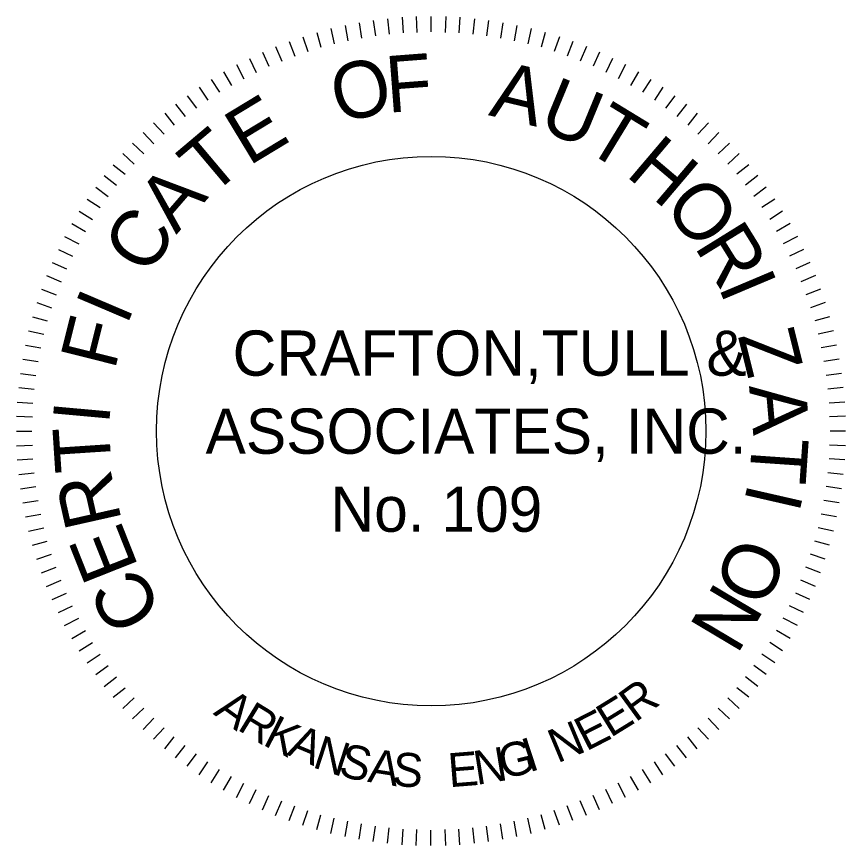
# Model space of a CAD drawing. Extents: x 6028666 to 6031787, y 5366484 to 5368484.
# Drawn here: x 6031045.9 to 6031317.1, y 5366759.6 to 5367030.8 of the extents above; entities that cross this region are included whole.
import ezdxf

# ---------------------------------------------------------------- set-up
doc = ezdxf.new("R2010")
doc.units = 0
doc.layers.add('R_Border Prem', color=7, linetype='Continuous')

msp = doc.modelspace()

# ---------------------------------------------------------------- linework, layer by layer
at = {"layer": 'R_Border Prem'}
for p, q in [((6031162.65, 5367029.51), (6031163.39, 5367024.52)), ((6031167.28, 5367030.07), (6031167.83, 5367025.07)), ((6031172.09, 5367030.62), (6031172.46, 5367025.44)), ((6031176.71, 5367030.81), (6031176.9, 5367025.63)), ((6031181.52, 5367030.81), (6031181.52, 5367025.81)), ((6031186.33, 5367030.81), (6031186.15, 5367025.63)), ((6031190.96, 5367030.62), (6031190.59, 5367025.44)), ((6031195.77, 5367030.07), (6031195.21, 5367025.07)), ((6031200.39, 5367029.51), (6031199.65, 5367024.52)), ((6031148.78, 5367026.92), (6031149.89, 5367021.93)), ((6031153.4, 5367027.85), (6031154.33, 5367022.85)), ((6031158.03, 5367028.77), (6031158.77, 5367023.78)), ((6031205.02, 5367028.77), (6031204.28, 5367023.78)), ((6031209.64, 5367027.85), (6031208.72, 5367022.85)), ((6031214.27, 5367026.92), (6031213.16, 5367021.93)), ((6031139.53, 5367024.15), (6031141.19, 5367019.34)), ((6031144.15, 5367025.63), (6031145.45, 5367020.82)), ((6031218.89, 5367025.63), (6031217.6, 5367020.82)), ((6031223.52, 5367024.15), (6031221.85, 5367019.34)), ((6031130.65, 5367021), (6031132.68, 5367016.19)), ((6031135.09, 5367022.67), (6031136.94, 5367017.86)), ((6031227.96, 5367022.67), (6031226.11, 5367017.86)), ((6031232.4, 5367021), (6031230.36, 5367016.19)), ((6031126.39, 5367019.15), (6031128.43, 5367014.53)), ((6031236.65, 5367019.15), (6031234.62, 5367014.53)), ((6031122.14, 5367017.12), (6031124.36, 5367012.49)), ((6031240.91, 5367017.12), (6031238.69, 5367012.49)), ((6031113.63, 5367012.68), (6031116.22, 5367008.24)), ((6031117.88, 5367015.08), (6031120.29, 5367010.46)), ((6031245.16, 5367015.08), (6031242.76, 5367010.46)), ((6031249.42, 5367012.68), (6031246.83, 5367008.24)), ((6031109.56, 5367010.27), (6031112.33, 5367006.02)), ((6031253.49, 5367010.27), (6031250.71, 5367006.02)), ((6031105.67, 5367007.68), (6031108.45, 5367003.43)), ((6031257.37, 5367007.68), (6031254.6, 5367003.43)), ((6031101.79, 5367004.91), (6031104.75, 5367000.84)), ((6031261.26, 5367004.91), (6031258.3, 5367000.84)), ((6031097.9, 5367002.13), (6031101.05, 5366998.06)), ((6031265.14, 5367002.13), (6031262, 5366998.06)), ((6031094.39, 5366999.17), (6031097.53, 5366995.29)), ((6031268.66, 5366999.17), (6031265.51, 5366995.29)), ((6031090.69, 5366996.03), (6031094.2, 5366992.33)), ((6031272.36, 5366996.03), (6031268.84, 5366992.33)), ((6031087.36, 5366992.88), (6031090.87, 5366989.18)), ((6031275.69, 5366992.88), (6031272.17, 5366989.18)), ((6031083.84, 5366989.37), (6031087.54, 5366985.85)), ((6031279.2, 5366989.37), (6031275.5, 5366985.85)), ((6031080.7, 5366986.04), (6031084.4, 5366982.52)), ((6031282.35, 5366986.04), (6031278.65, 5366982.52)), ((6031077.55, 5366982.34), (6031081.44, 5366979.19)), ((6031285.49, 5366982.34), (6031281.61, 5366979.19)), ((6031074.59, 5366978.82), (6031078.66, 5366975.68)), ((6031288.45, 5366978.82), (6031284.38, 5366975.68)), ((6031071.82, 5366974.94), (6031075.89, 5366971.98)), ((6031291.23, 5366974.94), (6031287.16, 5366971.98)), ((6031069.04, 5366971.05), (6031073.3, 5366968.28)), ((6031294, 5366971.05), (6031289.75, 5366968.28)), ((6031066.45, 5366967.17), (6031070.71, 5366964.39)), ((6031296.59, 5366967.17), (6031292.34, 5366964.39)), ((6031064.05, 5366963.1), (6031068.49, 5366960.51)), ((6031299, 5366963.1), (6031294.56, 5366960.51)), ((6031061.64, 5366958.84), (6031066.27, 5366956.44)), ((6031301.4, 5366958.84), (6031296.78, 5366956.44)), ((6031059.61, 5366954.59), (6031064.23, 5366952.37)), ((6031303.44, 5366954.59), (6031298.81, 5366952.37)), ((6031057.57, 5366950.33), (6031062.2, 5366948.3)), ((6031305.47, 5366950.33), (6031300.85, 5366948.3)), ((6031055.72, 5366946.08), (6031060.53, 5366944.04)), ((6031307.32, 5366946.08), (6031302.51, 5366944.04)), ((6031054.06, 5366941.64), (6031058.87, 5366939.79)), ((6031308.99, 5366941.64), (6031304.18, 5366939.79)), ((6031052.58, 5366937.2), (6031057.39, 5366935.53)), ((6031310.47, 5366937.2), (6031305.66, 5366935.53)), ((6031051.1, 5366932.57), (6031055.91, 5366931.28)), ((6031311.95, 5366932.57), (6031307.14, 5366931.28)), ((6031049.8, 5366927.95), (6031054.8, 5366926.84)), ((6031313.24, 5366927.95), (6031308.25, 5366926.84)), ((6031048.88, 5366923.32), (6031053.87, 5366922.4)), ((6031314.17, 5366923.32), (6031309.17, 5366922.4)), ((6031047.95, 5366918.7), (6031052.95, 5366917.96)), ((6031315.09, 5366918.7), (6031310.1, 5366917.96)), ((6031047.21, 5366914.07), (6031052.21, 5366913.33)), ((6031315.83, 5366914.07), (6031310.84, 5366913.33)), ((6031046.66, 5366909.45), (6031051.65, 5366908.89)), ((6031316.39, 5366909.45), (6031311.39, 5366908.89)), ((6031046.1, 5366904.64), (6031051.28, 5366904.27)), ((6031316.94, 5366904.64), (6031311.76, 5366904.27)), ((6031045.92, 5366900.01), (6031051.1, 5366899.83)), ((6031317.13, 5366900.01), (6031311.95, 5366899.83)), ((6031045.92, 5366895.2), (6031050.91, 5366895.2)), ((6031317.13, 5366895.2), (6031312.13, 5366895.2)), ((6031045.92, 5366890.39), (6031051.1, 5366890.58)), ((6031317.13, 5366890.39), (6031311.95, 5366890.58)), ((6031046.1, 5366885.77), (6031051.28, 5366886.14)), ((6031316.94, 5366885.77), (6031311.76, 5366886.14)), ((6031046.66, 5366880.96), (6031051.65, 5366881.51)), ((6031316.39, 5366880.96), (6031311.39, 5366881.51)), ((6031047.21, 5366876.33), (6031052.21, 5366877.07)), ((6031315.83, 5366876.33), (6031310.84, 5366877.07)), ((6031047.95, 5366871.71), (6031052.95, 5366872.45)), ((6031315.09, 5366871.71), (6031310.1, 5366872.45)), ((6031048.88, 5366867.08), (6031053.87, 5366868.01)), ((6031314.17, 5366867.08), (6031309.17, 5366868.01)), ((6031049.8, 5366862.46), (6031054.8, 5366863.57)), ((6031313.24, 5366862.46), (6031308.25, 5366863.57)), ((6031051.1, 5366857.83), (6031055.91, 5366859.13)), ((6031311.95, 5366857.83), (6031307.14, 5366859.13)), ((6031052.58, 5366853.21), (6031057.39, 5366854.87)), ((6031310.47, 5366853.21), (6031305.66, 5366854.87)), ((6031054.06, 5366848.77), (6031058.87, 5366850.62)), ((6031308.99, 5366848.77), (6031304.18, 5366850.62)), ((6031055.72, 5366844.33), (6031060.53, 5366846.36)), ((6031307.32, 5366844.33), (6031302.51, 5366846.36)), ((6031057.57, 5366840.07), (6031062.2, 5366842.11)), ((6031305.47, 5366840.07), (6031300.85, 5366842.11)), ((6031059.61, 5366835.82), (6031064.23, 5366838.04)), ((6031303.44, 5366835.82), (6031298.81, 5366838.04)), ((6031061.64, 5366831.56), (6031066.27, 5366833.97)), ((6031301.4, 5366831.56), (6031296.78, 5366833.97)), ((6031064.05, 5366827.31), (6031068.49, 5366829.9)), ((6031299, 5366827.31), (6031294.56, 5366829.9)), ((6031066.45, 5366823.24), (6031070.71, 5366826.01)), ((6031296.59, 5366823.24), (6031292.34, 5366826.01)), ((6031069.04, 5366819.35), (6031073.3, 5366822.13)), ((6031294, 5366819.35), (6031289.75, 5366822.13)), ((6031071.82, 5366815.47), (6031075.89, 5366818.43)), ((6031291.23, 5366815.47), (6031287.16, 5366818.43)), ((6031074.59, 5366811.58), (6031078.66, 5366814.73)), ((6031288.45, 5366811.58), (6031284.38, 5366814.73)), ((6031077.55, 5366808.07), (6031081.44, 5366811.21)), ((6031285.49, 5366808.07), (6031281.61, 5366811.21)), ((6031080.7, 5366804.37), (6031084.4, 5366807.88)), ((6031282.35, 5366804.37), (6031278.65, 5366807.88)), ((6031083.84, 5366801.04), (6031087.54, 5366804.55)), ((6031279.2, 5366801.04), (6031275.5, 5366804.55)), ((6031087.36, 5366797.52), (6031090.87, 5366801.22)), ((6031275.69, 5366797.52), (6031272.17, 5366801.22)), ((6031090.69, 5366794.38), (6031094.2, 5366798.08)), ((6031272.36, 5366794.38), (6031268.84, 5366798.08)), ((6031094.39, 5366791.23), (6031097.53, 5366795.12)), ((6031268.66, 5366791.23), (6031265.51, 5366795.12)), ((6031097.9, 5366788.27), (6031101.05, 5366792.34)), ((6031265.14, 5366788.27), (6031262, 5366792.34)), ((6031101.79, 5366785.5), (6031104.75, 5366789.57)), ((6031261.26, 5366785.5), (6031258.3, 5366789.57)), ((6031105.67, 5366782.72), (6031108.45, 5366786.98)), ((6031257.37, 5366782.72), (6031254.6, 5366786.98)), ((6031109.56, 5366780.13), (6031112.33, 5366784.39)), ((6031113.63, 5366777.73), (6031116.22, 5366782.17)), ((6031249.42, 5366777.73), (6031246.83, 5366782.17)), ((6031253.49, 5366780.13), (6031250.71, 5366784.39)), ((6031117.88, 5366775.32), (6031120.29, 5366779.95)), ((6031245.16, 5366775.32), (6031242.76, 5366779.95)), ((6031122.14, 5366773.29), (6031124.36, 5366777.91)), ((6031240.91, 5366773.29), (6031238.69, 5366777.91)), ((6031126.39, 5366771.25), (6031128.43, 5366775.88)), ((6031130.65, 5366769.4), (6031132.68, 5366774.21)), ((6031232.4, 5366769.4), (6031230.36, 5366774.21)), ((6031236.65, 5366771.25), (6031234.62, 5366775.88)), ((6031135.09, 5366767.74), (6031136.94, 5366772.55)), ((6031227.96, 5366767.74), (6031226.11, 5366772.55)), ((6031139.53, 5366766.26), (6031141.19, 5366771.07)), ((6031144.15, 5366764.78), (6031145.45, 5366769.59)), ((6031218.89, 5366764.78), (6031217.6, 5366769.59)), ((6031223.52, 5366766.26), (6031221.85, 5366771.07)), ((6031148.78, 5366763.48), (6031149.89, 5366768.48)), ((6031153.4, 5366762.56), (6031154.33, 5366767.55)), ((6031158.03, 5366761.63), (6031158.77, 5366766.63)), ((6031162.65, 5366760.89), (6031163.39, 5366765.89)), ((6031200.39, 5366760.89), (6031199.65, 5366765.89)), ((6031205.02, 5366761.63), (6031204.28, 5366766.63)), ((6031209.64, 5366762.56), (6031208.72, 5366767.55)), ((6031214.27, 5366763.48), (6031213.16, 5366768.48)), ((6031167.28, 5366760.34), (6031167.83, 5366765.33)), ((6031172.09, 5366759.78), (6031172.46, 5366764.96)), ((6031176.71, 5366759.6), (6031176.9, 5366764.78)), ((6031181.52, 5366759.6), (6031181.52, 5366764.59)), ((6031186.33, 5366759.6), (6031186.15, 5366764.78)), ((6031190.96, 5366759.78), (6031190.59, 5366764.96)), ((6031195.77, 5366760.34), (6031195.21, 5366765.33))]:
    msp.add_line(p, q, dxfattribs=at)
msp.add_circle((6031181.6, 5366895.16), 89.89, dxfattribs=at)

# ---------------------------------------------------------------- texts
for s, height, rotation, p in [('F', 18.5, 4.3732, (6031167.36, 5366999.31)), ('O', 18.5, 13.3113, (6031151.26, 5366995.8)), ('A', 18.5, 346.4969, (6031200.1, 5366998.57)), ('U', 18.5, 337.5588, (6031216.01, 5366994.32)), ('E', 18.5, 31.1876, (6031121.85, 5366981.74)), ('T', 18.5, 328.6206, (6031231, 5366987.66)), ('T', 18.5, 40.1257, (6031109.27, 5366971.56)), ('H', 18.5, 319.6825, (6031244.87, 5366978.96)), ('A', 18.5, 49.0639, (6031098.17, 5366959.35)), ('O', 18.5, 310.7444, (6031257.08, 5366968.23)), ('C', 18.5, 58.002, (6031089.1, 5366945.48)), ('R', 18.5, 301.8062, (6031267.44, 5366955.65)), ('I', 18.5, 292.8681, (6031275.4, 5366942.52)), ('I', 18.5, 66.9402, (6031081.89, 5366929.38)), ('F', 18.5, 75.8783, (6031078, 5366914.77)), ('Z', 18.5, 283.9299, (6031281.87, 5366926.42)), ('A', 18.5, 274.9918, (6031285.57, 5366909.96)), ('I', 18.5, 84.8164, (6031076.15, 5366897.01)), ('T', 18.5, 93.7546, (6031077.08, 5366882.21)), ('T', 18.5, 266.0537, (6031286.68, 5366893.68)), ('R', 18.5, 102.6927, (6031080.41, 5366865.74)), ('I', 18.5, 257.1155, (6031285.39, 5366878.69)), ('E', 18.5, 111.6308, (6031085.96, 5366850.57)), ('O', 18.5, 248.1774, (6031281.13, 5366861.67)), ('C', 18.5, 120.569, (6031094.1, 5366836.33)), ('N', 18.5, 239.2393, (6031274.84, 5366846.5)), ('R', 11.1, 36.1806, (6031248.39, 5366799.7)), ('A', 11.1, 324.001, (6031110.01, 5366802.66)), ('E', 11.1, 31.6694, (6031240.25, 5366794.7)), ('R', 11.1, 328.5123, (6031117.78, 5366797.66)), ('E', 11.1, 27.1582, (6031232.29, 5366790.26)), ('K', 11.1, 333.0235, (6031126.1, 5366792.67)), ('N', 11.1, 22.647, (6031222.86, 5366786.38)), ('A', 11.1, 337.5347, (6031134.06, 5366789.34)), ('N', 11.1, 342.0459, (6031142.38, 5366785.27)), ('G', 11.1, 13.6245, (6031205.1, 5366781.2)), ('I', 11.1, 18.1357, (6031213.61, 5366783.42)), ('S', 11.1, 346.5572, (6031150.89, 5366782.49)), ('A', 11.1, 351.0684, (6031160.51, 5366780.46)), ('E', 11.1, 4.6021, (6031187.52, 5366778.61)), ('N', 11.1, 9.1133, (6031196.4, 5366779.35)), ('S', 11.1, 355.5796, (6031168.65, 5366779.16))]:
    msp.add_text(s, height=height, rotation=rotation, dxfattribs=at).set_placement(p)
for s, height, p in [('CRAFTON,TULL &', 14.7996, (6031116.61, 5366913.29)), ('ASSOCIATES, INC.', 14.7996, (6031107.75, 5366887.76)), ('No. 109', 14.8, (6031148.63, 5366862.23))]:
    msp.add_text(s, height=height, dxfattribs=at).set_placement(p)

doc.saveas('drawing.dxf')
